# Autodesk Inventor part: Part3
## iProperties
Created: 2002-04
Part Number: Part3
Document SubType Name: Sheet Metal
Control State: 0
Master: False
Checked Out: False
Shininess: 77.0
Angle Display Precision: 2
Document Length Units: 11269
Document Angle Units: 11279
Document Time Units: 11290
Document Mass Units: 11283
Document Length Units Precision: 3
Document Angle Units Precision: 2
Density: 0.0
Volumn: 0.0
Area: 0.0
PropertySet Name: Model Information
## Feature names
1. Corner Chamfer1
2. Corner Chamfer2
3. Plate1
4. Plate6
5. Bend5
6. Plate7
7. Bend7
8. Cut1
